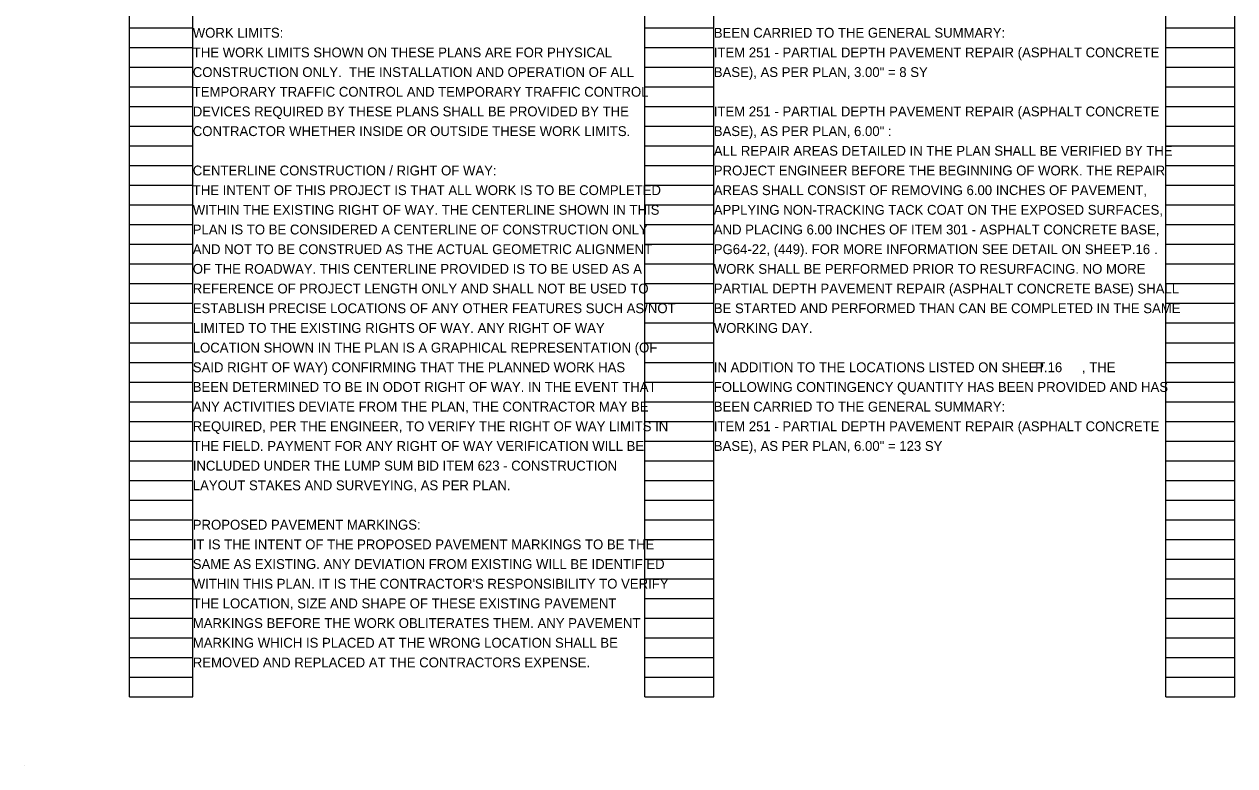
# Model space of a CAD drawing. Extents: x 28776.5 to 28808.5, y 9178.8 to 9230.7.
# Drawn here: x 28776.53 to 28793.77, y 9209.6 to 9220.15 of the extents above; entities that cross this region are included whole.
import ezdxf

# ---------------------------------------------------------------- set-up
doc = ezdxf.new("R2010")
doc.units = 0
doc.layers.add('SH_Data', color=7, linetype='Continuous')
doc.layers.add('SH_Text', color=7, linetype='Continuous')

msp = doc.modelspace()

# ---------------------------------------------------------------- linework, layer by layer
at = {"layer": 'SH_Data'}
for p, q in [((28778.029, 9210.582), (28778.029, 9230.742)), ((28778.929, 9210.582), (28778.929, 9230.742)), ((28785.369, 9210.582), (28785.369, 9230.742)), ((28786.349, 9210.582), (28786.349, 9230.742)), ((28792.789, 9210.582), (28792.789, 9230.742)), ((28793.769, 9210.582), (28793.769, 9230.742)), ((28778.029, 9220.102), (28778.929, 9220.102)), ((28785.369, 9220.102), (28786.349, 9220.102)), ((28792.789, 9220.102), (28793.769, 9220.102)), ((28778.029, 9219.822), (28778.929, 9219.822)), ((28785.369, 9219.822), (28786.349, 9219.822)), ((28792.789, 9219.822), (28793.769, 9219.822)), ((28778.029, 9219.542), (28778.929, 9219.542)), ((28785.369, 9219.542), (28786.349, 9219.542)), ((28792.789, 9219.542), (28793.769, 9219.542)), ((28778.029, 9219.262), (28778.929, 9219.262)), ((28785.369, 9219.262), (28786.349, 9219.262)), ((28792.789, 9219.262), (28793.769, 9219.262)), ((28778.029, 9218.982), (28778.929, 9218.982)), ((28785.369, 9218.982), (28786.349, 9218.982)), ((28792.789, 9218.982), (28793.769, 9218.982)), ((28778.029, 9218.702), (28778.929, 9218.702)), ((28785.369, 9218.702), (28786.349, 9218.702)), ((28792.789, 9218.702), (28793.769, 9218.702)), ((28778.029, 9218.422), (28778.929, 9218.422)), ((28785.369, 9218.422), (28786.349, 9218.422)), ((28792.789, 9218.422), (28793.769, 9218.422)), ((28778.029, 9218.142), (28778.929, 9218.142)), ((28785.369, 9218.142), (28786.349, 9218.142)), ((28792.789, 9218.142), (28793.769, 9218.142)), ((28778.029, 9217.862), (28778.929, 9217.862)), ((28785.369, 9217.862), (28786.349, 9217.862)), ((28792.789, 9217.862), (28793.769, 9217.862)), ((28778.029, 9217.582), (28778.929, 9217.582)), ((28785.369, 9217.582), (28786.349, 9217.582)), ((28792.789, 9217.582), (28793.769, 9217.582)), ((28778.029, 9217.302), (28778.929, 9217.302)), ((28785.369, 9217.302), (28786.349, 9217.302)), ((28792.789, 9217.302), (28793.769, 9217.302)), ((28778.029, 9217.022), (28778.929, 9217.022)), ((28785.369, 9217.022), (28786.349, 9217.022)), ((28792.789, 9217.022), (28793.769, 9217.022)), ((28778.029, 9216.742), (28778.929, 9216.742)), ((28785.369, 9216.742), (28786.349, 9216.742)), ((28792.789, 9216.742), (28793.769, 9216.742)), ((28778.029, 9216.462), (28778.929, 9216.462)), ((28785.369, 9216.462), (28786.349, 9216.462)), ((28792.789, 9216.462), (28793.769, 9216.462)), ((28778.029, 9216.182), (28778.929, 9216.182)), ((28785.369, 9216.182), (28786.349, 9216.182)), ((28792.789, 9216.182), (28793.769, 9216.182)), ((28778.029, 9215.902), (28778.929, 9215.902)), ((28785.369, 9215.902), (28786.349, 9215.902)), ((28792.789, 9215.902), (28793.769, 9215.902)), ((28778.029, 9215.622), (28778.929, 9215.622)), ((28785.369, 9215.622), (28786.349, 9215.622)), ((28792.789, 9215.622), (28793.769, 9215.622)), ((28778.029, 9215.342), (28778.929, 9215.342)), ((28785.369, 9215.342), (28786.349, 9215.342)), ((28792.789, 9215.342), (28793.769, 9215.342)), ((28778.029, 9215.062), (28778.929, 9215.062)), ((28785.369, 9215.062), (28786.349, 9215.062)), ((28792.789, 9215.062), (28793.769, 9215.062)), ((28778.029, 9214.782), (28778.929, 9214.782)), ((28785.369, 9214.782), (28786.349, 9214.782)), ((28792.789, 9214.782), (28793.769, 9214.782)), ((28778.029, 9214.502), (28778.929, 9214.502)), ((28785.369, 9214.502), (28786.349, 9214.502)), ((28792.789, 9214.502), (28793.769, 9214.502)), ((28778.029, 9214.222), (28778.929, 9214.222)), ((28785.369, 9214.222), (28786.349, 9214.222)), ((28792.789, 9214.222), (28793.769, 9214.222)), ((28778.029, 9213.942), (28778.929, 9213.942)), ((28785.369, 9213.942), (28786.349, 9213.942)), ((28792.789, 9213.942), (28793.769, 9213.942)), ((28778.029, 9213.662), (28778.929, 9213.662)), ((28785.369, 9213.662), (28786.349, 9213.662)), ((28792.789, 9213.662), (28793.769, 9213.662)), ((28778.029, 9213.382), (28778.929, 9213.382)), ((28785.369, 9213.382), (28786.349, 9213.382)), ((28792.789, 9213.382), (28793.769, 9213.382)), ((28778.029, 9213.102), (28778.929, 9213.102)), ((28785.369, 9213.102), (28786.349, 9213.102)), ((28792.789, 9213.102), (28793.769, 9213.102)), ((28778.029, 9212.822), (28778.929, 9212.822)), ((28785.369, 9212.822), (28786.349, 9212.822)), ((28792.789, 9212.822), (28793.769, 9212.822)), ((28778.029, 9212.542), (28778.929, 9212.542)), ((28785.369, 9212.542), (28786.349, 9212.542)), ((28792.789, 9212.542), (28793.769, 9212.542)), ((28778.029, 9212.262), (28778.929, 9212.262)), ((28785.369, 9212.262), (28786.349, 9212.262)), ((28792.789, 9212.262), (28793.769, 9212.262)), ((28778.029, 9211.982), (28778.929, 9211.982)), ((28785.369, 9211.982), (28786.349, 9211.982)), ((28792.789, 9211.982), (28793.769, 9211.982)), ((28778.029, 9211.702), (28778.929, 9211.702)), ((28785.369, 9211.702), (28786.349, 9211.702)), ((28792.789, 9211.702), (28793.769, 9211.702)), ((28778.029, 9211.422), (28778.929, 9211.422)), ((28785.369, 9211.422), (28786.349, 9211.422)), ((28792.789, 9211.422), (28793.769, 9211.422)), ((28778.029, 9211.142), (28778.929, 9211.142)), ((28785.369, 9211.142), (28786.349, 9211.142)), ((28792.789, 9211.142), (28793.769, 9211.142)), ((28778.029, 9210.862), (28778.929, 9210.862)), ((28785.369, 9210.862), (28786.349, 9210.862)), ((28792.789, 9210.862), (28793.769, 9210.862)), ((28778.029, 9210.582), (28778.929, 9210.582)), ((28785.369, 9210.582), (28786.349, 9210.582)), ((28792.789, 9210.582), (28793.769, 9210.582)), ((28776.529, 9209.602), (28776.529, 9209.602))]:
    msp.add_line(p, q, dxfattribs=at)

# ---------------------------------------------------------------- texts
at = {"layer": 'SH_Text'}
for s, p in [('WORK LIMITS:', (28778.929, 9219.962)), ('BEEN CARRIED TO THE GENERAL SUMMARY:', (28786.349, 9219.962)), ('THE WORK LIMITS SHOWN ON THESE PLANS ARE FOR PHYSICAL ', (28778.929, 9219.682)), ('ITEM 251 - PARTIAL DEPTH PAVEMENT REPAIR (ASPHALT CONCRETE ', (28786.349, 9219.682)), ('CONSTRUCTION ONLY.  THE INSTALLATION AND OPERATION OF ALL ', (28778.929, 9219.402)), ('BASE), AS PER PLAN, 3.00" = 8 SY', (28786.349, 9219.402)), ('TEMPORARY TRAFFIC CONTROL AND TEMPORARY TRAFFIC CONTROL ', (28778.929, 9219.122)), ('DEVICES REQUIRED BY THESE PLANS SHALL BE PROVIDED BY THE ', (28778.929, 9218.842)), ('ITEM 251 - PARTIAL DEPTH PAVEMENT REPAIR (ASPHALT CONCRETE ', (28786.349, 9218.842)), ('CONTRACTOR WHETHER INSIDE OR OUTSIDE THESE WORK LIMITS.', (28778.929, 9218.562)), ('BASE), AS PER PLAN, 6.00" :', (28786.349, 9218.562)), ('ALL REPAIR AREAS DETAILED IN THE PLAN SHALL BE VERIFIED BY THE ', (28786.349, 9218.282)), ('CENTERLINE CONSTRUCTION / RIGHT OF WAY:', (28778.929, 9218.002)), ('PROJECT ENGINEER BEFORE THE BEGINNING OF WORK. THE REPAIR ', (28786.349, 9218.002)), ('THE INTENT OF THIS PROJECT IS THAT ALL WORK IS TO BE COMPLETED ', (28778.929, 9217.722)), ('AREAS SHALL CONSIST OF REMOVING 6.00 INCHES OF PAVEMENT, ', (28786.349, 9217.722)), ('WITHIN THE EXISTING RIGHT OF WAY. THE CENTERLINE SHOWN IN THIS ', (28778.929, 9217.442)), ('APPLYING NON-TRACKING TACK COAT ON THE EXPOSED SURFACES,  ', (28786.349, 9217.442)), ('PLAN IS TO BE CONSIDERED A CENTERLINE OF CONSTRUCTION ONLY ', (28778.929, 9217.162)), ('AND PLACING 6.00 INCHES OF ITEM 301 - ASPHALT CONCRETE BASE, ', (28786.349, 9217.162)), ('AND NOT TO BE CONSTRUED AS THE ACTUAL GEOMETRIC ALIGNMENT ', (28778.929, 9216.882)), ('PG64-22, (449). FOR MORE INFORMATION SEE DETAIL ON SHEET', (28786.349, 9216.882)), ('P.16', (28792.178, 9216.882)), ('          . ', (28792.1, 9216.882)), ('OF THE ROADWAY. THIS CENTERLINE PROVIDED IS TO BE USED AS A ', (28778.929, 9216.602)), ('WORK SHALL BE PERFORMED PRIOR TO RESURFACING. NO MORE ', (28786.349, 9216.602)), ('REFERENCE OF PROJECT LENGTH ONLY AND SHALL NOT BE USED TO ', (28778.929, 9216.322)), ('PARTIAL DEPTH PAVEMENT REPAIR (ASPHALT CONCRETE BASE) SHALL ', (28786.349, 9216.322)), ('ESTABLISH PRECISE LOCATIONS OF ANY OTHER FEATURES SUCH AS/NOT ', (28778.929, 9216.042)), ('BE STARTED AND PERFORMED THAN CAN BE COMPLETED IN THE SAME ', (28786.349, 9216.042)), ('LIMITED TO THE EXISTING RIGHTS OF WAY. ANY RIGHT OF WAY ', (28778.929, 9215.762)), ('WORKING DAY.', (28786.349, 9215.762)), ('LOCATION SHOWN IN THE PLAN IS A GRAPHICAL REPRESENTATION (OF ', (28778.929, 9215.482)), ('SAID RIGHT OF WAY) CONFIRMING THAT THE PLANNED WORK HAS ', (28778.929, 9215.202)), ('IN ADDITION TO THE LOCATIONS LISTED ON SHEET          , THE ', (28786.349, 9215.202)), ('P.16', (28790.926, 9215.202)), ('BEEN DETERMINED TO BE IN ODOT RIGHT OF WAY. IN THE EVENT THAT ', (28778.929, 9214.922)), ('FOLLOWING CONTINGENCY QUANTITY HAS BEEN PROVIDED AND HAS ', (28786.349, 9214.922)), ('ANY ACTIVITIES DEVIATE FROM THE PLAN, THE CONTRACTOR MAY BE ', (28778.929, 9214.642)), ('BEEN CARRIED TO THE GENERAL SUMMARY:', (28786.349, 9214.642)), ('REQUIRED, PER THE ENGINEER, TO VERIFY THE RIGHT OF WAY LIMITS IN ', (28778.929, 9214.362)), ('ITEM 251 - PARTIAL DEPTH PAVEMENT REPAIR (ASPHALT CONCRETE ', (28786.349, 9214.362)), ('THE FIELD. PAYMENT FOR ANY RIGHT OF WAY VERIFICATION WILL BE ', (28778.929, 9214.082)), ('BASE), AS PER PLAN, 6.00" = 123 SY', (28786.349, 9214.082)), ('INCLUDED UNDER THE LUMP SUM BID ITEM 623 - CONSTRUCTION ', (28778.929, 9213.802)), ('LAYOUT STAKES AND SURVEYING, AS PER PLAN.', (28778.929, 9213.522)), ('PROPOSED PAVEMENT MARKINGS:', (28778.929, 9212.962)), ('IT IS THE INTENT OF THE PROPOSED PAVEMENT MARKINGS TO BE THE ', (28778.929, 9212.682)), ('SAME AS EXISTING. ANY DEVIATION FROM EXISTING WILL BE IDENTIFIED ', (28778.929, 9212.402)), ("WITHIN THIS PLAN. IT IS THE CONTRACTOR'S RESPONSIBILITY TO VERIFY ", (28778.929, 9212.122)), ('THE LOCATION, SIZE AND SHAPE OF THESE EXISTING PAVEMENT ', (28778.929, 9211.842)), ('MARKINGS BEFORE THE WORK OBLITERATES THEM. ANY PAVEMENT ', (28778.929, 9211.562)), ('MARKING WHICH IS PLACED AT THE WRONG LOCATION SHALL BE ', (28778.929, 9211.282)), ('REMOVED AND REPLACED AT THE CONTRACTORS EXPENSE.', (28778.929, 9211.002))]:
    msp.add_text(s, height=0.14, dxfattribs=at).set_placement(p)

doc.saveas('drawing.dxf')
